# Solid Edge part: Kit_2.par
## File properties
Author: ahadarics
Last saved by: ahadarics
Revision: 76
Sűrűség: 0,000 kg/m^3
Pontosság: 0,990
Username: ahadarics
Dokumentum tartalom típus: 0
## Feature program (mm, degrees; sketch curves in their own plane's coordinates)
base feature "unnamed BaseFeature 1"
sketch for "Furat_1" plane through (0, 3.75, 13.5) normal (0, 0, 1) x-axis (0, 1, 0)
  hole centre (-0.25, 0) bore radius 4.283
hole "Furat_1" nominal diameter 9.728 finite  ThreadDepth = 7.5 mm
chamfer "Letörés_1" setback 0.7
sketch for "unnamed Protrusion 1" #1 plane through (0, 33.5, 0) normal (0, 1, 0) x-axis (0, 0, -1)
  line (-7.5498, -8) -> (7.5498, -8)
  arc centre (0, 0) radius 11 from (7.5498, -8) to (-7.5498, -8) cw
sketch for "unnamed Protrusion 1" #2 plane through (0, 33.5, 0) normal (0, 1, 0) x-axis (0, 0, -1)
  line (7.5498, 8) -> (-7.5498, 8)
extrude "unnamed Protrusion 1" add to key point along -normal
thread "unnamed Thread 1"
chamfer "Letörés_2" setback 1.5
sketch for "Kivágás_1" #1 plane through (0, 33.5, 0) normal (0, 1, 0) x-axis (0, 0, -1)
  line (-7.5498, -8) -> (7.5498, -8)
  arc centre (0, 0) radius 11 from (7.5498, -8) to (-7.5498, -8) cw
sketch for "Kivágás_1" #2 plane through (0, 33.5, 0) normal (0, 1, 0) x-axis (0, 0, -1)
  line (7.5498, 8) -> (-7.5498, 8)
extrude "Kivágás_1" cut finite 20 along -normal
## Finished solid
Body 1: solid body, 32 faces, 72 edges, 41 vertices.
  Faces by surface: plane 13, cylinder 11, cone 8
  Edges by curve: line 33, circle 31, intersection 4, spline 4
Bounding box of the edges (mm): 30.000 x 39.500 x 28.500, from (-15, -6, -15) to (15, 33.5, 13.5).
Cylindrical faces by radius (mm): R4 x1, R4.28 x1, R4.283 x1, R9.85 x2, R11 x4, R13.5 x1, R15 x1
Conical faces (half-angle, radius in mm at the cone's reference point): 45 deg R4.1 x2, 45 deg R4.983 x1, 45 deg R11 x2, 59 deg R2.1415 x1, 60 deg R10.425 x2
Planar faces by outward normal: +x 1, +y 7, +z 2, -x 1, -y 2
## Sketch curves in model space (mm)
arc centre (0, 33.5, 0) radius 11 from (8, 33.5, -7.5498) through (11, 33.5, 0) to (8, 33.5, 7.5498)
line (8, 33.5, 7.5498) -> (8, 33.5, -7.5498)
arc centre (0, 33.5, 0) radius 11 from (-8, 33.5, 7.5498) through (-11, 33.5, 0) to (-8, 33.5, -7.5498)
line (-8, 33.5, -7.5498) -> (-8, 33.5, 7.5498)
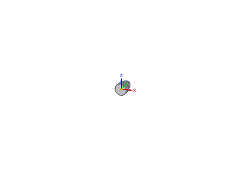
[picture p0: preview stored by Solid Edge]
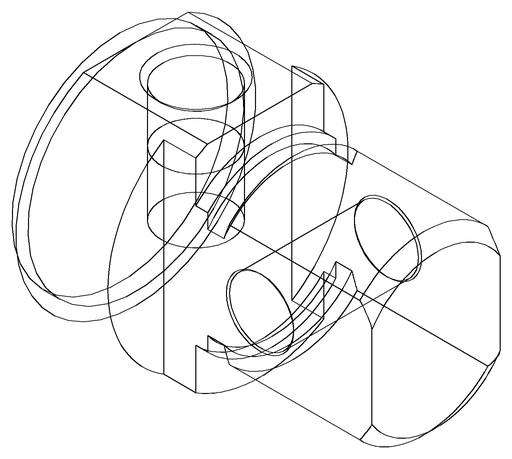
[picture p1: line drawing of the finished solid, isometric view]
